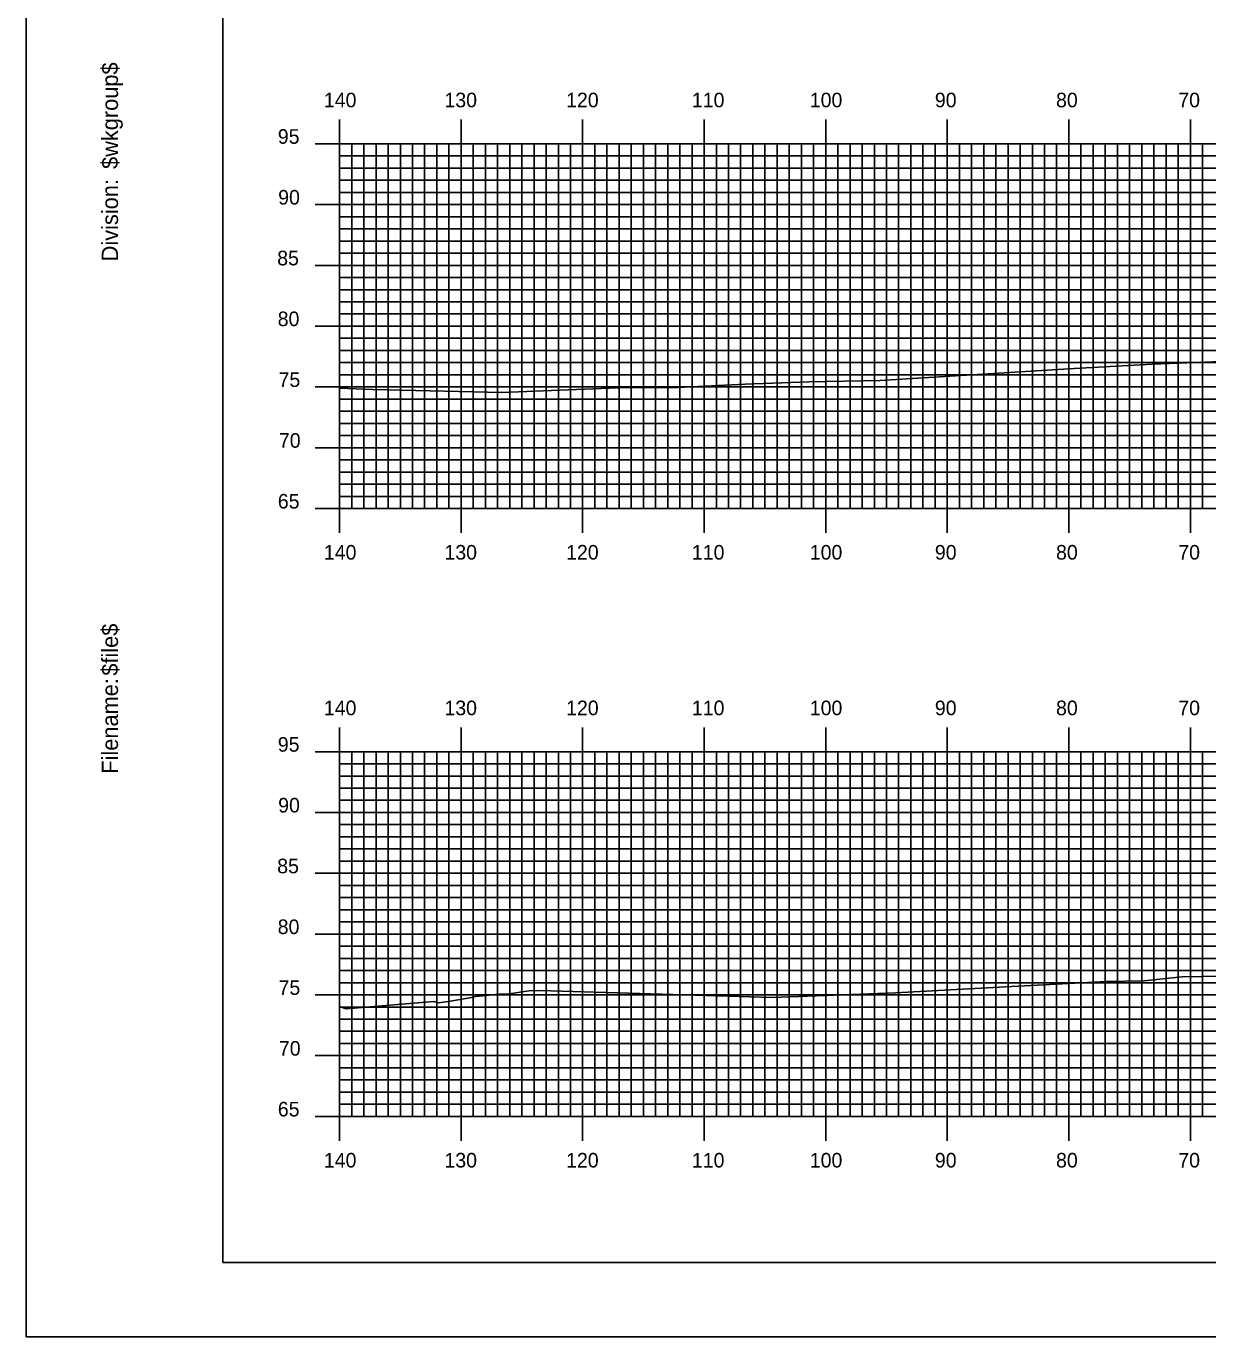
# Model space of a CAD drawing. Extents: x 1777138 to 1777481, y 442591 to 442811.
# Drawn here: x 1777138 to 1777235.2, y 442590.5 to 442698.3 of the extents above; entities that cross this region are included whole.
import ezdxf

# ---------------------------------------------------------------- set-up
doc = ezdxf.new("R2010")
doc.units = 0
for name, color, linetype in [('BORDER', 7, 'Continuous'), ('H_V ANNOTATION', 7, 'Continuous'), ('MAJOR', 7, 'Continuous'), ('MINOR', 7, 'Continuous'), ('PLOT BOUNDARY', 7, 'Continuous'), ('S_Roadway_Centerline', 7, 'Continuous')]:
    doc.layers.add(name, color=color, linetype=linetype)

msp = doc.modelspace()

# ---------------------------------------------------------------- linework, layer by layer
at = {"layer": 'BORDER'}
msp.add_lwpolyline([(1777154.16, 442596.67), (1777474.16, 442596.67), (1777474.16, 442806.67), (1777154.16, 442806.67)], close=True, dxfattribs=at)
at = {"layer": 'MAJOR'}
for p, q in [((1777163.76, 442690.67), (1777163.76, 442688.67)), ((1777173.76, 442690.67), (1777173.76, 442688.67)), ((1777183.76, 442690.67), (1777183.76, 442688.67)), ((1777193.76, 442690.67), (1777193.76, 442688.67)), ((1777203.76, 442690.67), (1777203.76, 442688.67)), ((1777213.76, 442690.67), (1777213.76, 442688.67)), ((1777223.76, 442690.67), (1777223.76, 442688.67)), ((1777233.76, 442690.67), (1777233.76, 442688.67)), ((1777161.76, 442688.67), (1777163.76, 442688.67)), ((1777163.76, 442688.67), (1777443.76, 442688.67)), ((1777163.76, 442658.67), (1777163.76, 442688.67)), ((1777163.76, 442658.67), (1777163.76, 442688.67)), ((1777163.76, 442688.67), (1777443.76, 442688.67)), ((1777173.76, 442658.67), (1777173.76, 442688.67)), ((1777183.76, 442658.67), (1777183.76, 442688.67)), ((1777193.76, 442658.67), (1777193.76, 442688.67)), ((1777203.76, 442658.67), (1777203.76, 442688.67)), ((1777213.76, 442658.67), (1777213.76, 442688.67)), ((1777223.76, 442658.67), (1777223.76, 442688.67)), ((1777233.76, 442658.67), (1777233.76, 442688.67)), ((1777161.76, 442683.67), (1777163.76, 442683.67)), ((1777163.76, 442683.67), (1777443.76, 442683.67)), ((1777161.76, 442678.67), (1777163.76, 442678.67)), ((1777163.76, 442678.67), (1777443.76, 442678.67)), ((1777161.76, 442673.67), (1777163.76, 442673.67)), ((1777163.76, 442673.67), (1777443.76, 442673.67)), ((1777161.76, 442668.67), (1777163.76, 442668.67)), ((1777163.76, 442668.67), (1777443.76, 442668.67)), ((1777161.76, 442663.67), (1777163.76, 442663.67)), ((1777163.76, 442663.67), (1777443.76, 442663.67)), ((1777161.76, 442658.67), (1777163.76, 442658.67)), ((1777163.76, 442658.67), (1777443.76, 442658.67)), ((1777163.76, 442658.67), (1777443.76, 442658.67)), ((1777163.76, 442656.66), (1777163.76, 442658.67)), ((1777173.76, 442656.66), (1777173.76, 442658.67)), ((1777183.76, 442656.66), (1777183.76, 442658.67)), ((1777193.76, 442656.66), (1777193.76, 442658.67)), ((1777203.76, 442656.66), (1777203.76, 442658.67)), ((1777213.76, 442656.66), (1777213.76, 442658.67)), ((1777223.76, 442656.66), (1777223.76, 442658.67)), ((1777233.76, 442656.66), (1777233.76, 442658.67)), ((1777163.76, 442640.67), (1777163.76, 442638.67)), ((1777173.76, 442640.67), (1777173.76, 442638.67)), ((1777183.76, 442640.67), (1777183.76, 442638.67)), ((1777193.76, 442640.67), (1777193.76, 442638.67)), ((1777203.76, 442640.67), (1777203.76, 442638.67)), ((1777213.76, 442640.67), (1777213.76, 442638.67)), ((1777223.76, 442640.67), (1777223.76, 442638.67)), ((1777233.76, 442640.67), (1777233.76, 442638.67)), ((1777161.76, 442638.67), (1777163.76, 442638.67)), ((1777163.76, 442638.67), (1777443.76, 442638.67)), ((1777163.76, 442608.67), (1777163.76, 442638.67)), ((1777163.76, 442608.67), (1777163.76, 442638.67)), ((1777163.76, 442638.67), (1777443.76, 442638.67)), ((1777173.76, 442608.67), (1777173.76, 442638.67)), ((1777183.76, 442608.67), (1777183.76, 442638.67)), ((1777193.76, 442608.67), (1777193.76, 442638.67)), ((1777203.76, 442608.67), (1777203.76, 442638.67)), ((1777213.76, 442608.67), (1777213.76, 442638.67)), ((1777223.76, 442608.67), (1777223.76, 442638.67)), ((1777233.76, 442608.67), (1777233.76, 442638.67)), ((1777161.76, 442633.67), (1777163.76, 442633.67)), ((1777163.76, 442633.67), (1777443.76, 442633.67)), ((1777161.76, 442628.67), (1777163.76, 442628.67)), ((1777163.76, 442628.67), (1777443.76, 442628.67)), ((1777161.76, 442623.67), (1777163.76, 442623.67)), ((1777163.76, 442623.67), (1777443.76, 442623.67)), ((1777161.76, 442618.67), (1777163.76, 442618.67)), ((1777163.76, 442618.67), (1777443.76, 442618.67)), ((1777161.76, 442613.67), (1777163.76, 442613.67)), ((1777163.76, 442613.67), (1777443.76, 442613.67)), ((1777161.76, 442608.67), (1777163.76, 442608.67)), ((1777163.76, 442608.67), (1777443.76, 442608.67)), ((1777163.76, 442608.67), (1777443.76, 442608.67)), ((1777163.76, 442606.66), (1777163.76, 442608.67)), ((1777173.76, 442606.66), (1777173.76, 442608.67)), ((1777183.76, 442606.66), (1777183.76, 442608.67)), ((1777193.76, 442606.66), (1777193.76, 442608.67)), ((1777203.76, 442606.66), (1777203.76, 442608.67)), ((1777213.76, 442606.66), (1777213.76, 442608.67)), ((1777223.76, 442606.66), (1777223.76, 442608.67)), ((1777233.76, 442606.66), (1777233.76, 442608.67))]:
    msp.add_line(p, q, dxfattribs=at)
at = {"layer": 'MINOR'}
for p, q in [((1777164.76, 442658.67), (1777164.76, 442688.67)), ((1777165.76, 442658.67), (1777165.76, 442688.67)), ((1777166.76, 442658.67), (1777166.76, 442688.67)), ((1777167.76, 442658.67), (1777167.76, 442688.67)), ((1777168.76, 442658.67), (1777168.76, 442688.67)), ((1777169.76, 442658.67), (1777169.76, 442688.67)), ((1777170.76, 442658.67), (1777170.76, 442688.67)), ((1777171.76, 442658.67), (1777171.76, 442688.67)), ((1777172.76, 442658.67), (1777172.76, 442688.67)), ((1777174.76, 442658.67), (1777174.76, 442688.67)), ((1777175.76, 442658.67), (1777175.76, 442688.67)), ((1777176.76, 442658.67), (1777176.76, 442688.67)), ((1777177.76, 442658.67), (1777177.76, 442688.67)), ((1777178.76, 442658.67), (1777178.76, 442688.67)), ((1777179.76, 442658.67), (1777179.76, 442688.67)), ((1777180.76, 442658.67), (1777180.76, 442688.67)), ((1777181.76, 442658.67), (1777181.76, 442688.67)), ((1777182.76, 442658.67), (1777182.76, 442688.67)), ((1777184.76, 442658.67), (1777184.76, 442688.67)), ((1777185.76, 442658.67), (1777185.76, 442688.67)), ((1777186.76, 442658.67), (1777186.76, 442688.67)), ((1777187.76, 442658.67), (1777187.76, 442688.67)), ((1777188.76, 442658.67), (1777188.76, 442688.67)), ((1777189.76, 442658.67), (1777189.76, 442688.67)), ((1777190.76, 442658.67), (1777190.76, 442688.67)), ((1777191.76, 442658.67), (1777191.76, 442688.67)), ((1777192.76, 442658.67), (1777192.76, 442688.67)), ((1777194.76, 442658.67), (1777194.76, 442688.67)), ((1777195.76, 442658.67), (1777195.76, 442688.67)), ((1777196.76, 442658.67), (1777196.76, 442688.67)), ((1777197.76, 442658.67), (1777197.76, 442688.67)), ((1777198.76, 442658.67), (1777198.76, 442688.67)), ((1777199.76, 442658.67), (1777199.76, 442688.67)), ((1777200.76, 442658.67), (1777200.76, 442688.67)), ((1777201.76, 442658.67), (1777201.76, 442688.67)), ((1777202.76, 442658.67), (1777202.76, 442688.67)), ((1777204.76, 442658.67), (1777204.76, 442688.67)), ((1777205.76, 442658.67), (1777205.76, 442688.67)), ((1777206.76, 442658.67), (1777206.76, 442688.67)), ((1777207.76, 442658.67), (1777207.76, 442688.67)), ((1777208.76, 442658.67), (1777208.76, 442688.67)), ((1777209.76, 442658.67), (1777209.76, 442688.67)), ((1777210.76, 442658.67), (1777210.76, 442688.67)), ((1777211.76, 442658.67), (1777211.76, 442688.67)), ((1777212.76, 442658.67), (1777212.76, 442688.67)), ((1777214.76, 442658.67), (1777214.76, 442688.67)), ((1777215.76, 442658.67), (1777215.76, 442688.67)), ((1777216.76, 442658.67), (1777216.76, 442688.67)), ((1777217.76, 442658.67), (1777217.76, 442688.67)), ((1777218.76, 442658.67), (1777218.76, 442688.67)), ((1777219.76, 442658.67), (1777219.76, 442688.67)), ((1777220.76, 442658.67), (1777220.76, 442688.67)), ((1777221.76, 442658.67), (1777221.76, 442688.67)), ((1777222.76, 442658.67), (1777222.76, 442688.67)), ((1777224.76, 442658.67), (1777224.76, 442688.67)), ((1777225.76, 442658.67), (1777225.76, 442688.67)), ((1777226.76, 442658.67), (1777226.76, 442688.67)), ((1777227.76, 442658.67), (1777227.76, 442688.67)), ((1777228.76, 442658.67), (1777228.76, 442688.67)), ((1777229.76, 442658.67), (1777229.76, 442688.67)), ((1777230.76, 442658.67), (1777230.76, 442688.67)), ((1777231.76, 442658.67), (1777231.76, 442688.67)), ((1777232.76, 442658.67), (1777232.76, 442688.67)), ((1777234.76, 442658.67), (1777234.76, 442688.67)), ((1777163.76, 442687.67), (1777443.76, 442687.67)), ((1777163.76, 442687.67), (1777165.77, 442687.67)), ((1777163.76, 442686.67), (1777443.76, 442686.67)), ((1777163.76, 442686.67), (1777165.77, 442686.67)), ((1777163.76, 442685.67), (1777443.76, 442685.67)), ((1777163.76, 442685.67), (1777165.77, 442685.67)), ((1777163.76, 442684.67), (1777443.76, 442684.67)), ((1777163.76, 442684.67), (1777165.77, 442684.67)), ((1777163.76, 442682.67), (1777443.76, 442682.67)), ((1777163.76, 442682.67), (1777165.77, 442682.67)), ((1777163.76, 442681.67), (1777443.76, 442681.67)), ((1777163.76, 442681.67), (1777165.77, 442681.67)), ((1777163.76, 442680.67), (1777443.76, 442680.67)), ((1777163.76, 442680.67), (1777165.77, 442680.67)), ((1777163.76, 442679.67), (1777443.76, 442679.67)), ((1777163.76, 442679.67), (1777165.77, 442679.67)), ((1777163.76, 442677.67), (1777443.76, 442677.67)), ((1777163.76, 442677.67), (1777165.77, 442677.67)), ((1777163.76, 442676.67), (1777443.76, 442676.67)), ((1777163.76, 442676.67), (1777165.77, 442676.67)), ((1777163.76, 442675.67), (1777443.76, 442675.67)), ((1777163.76, 442675.67), (1777165.77, 442675.67)), ((1777163.76, 442674.67), (1777443.76, 442674.67)), ((1777163.76, 442674.67), (1777165.77, 442674.67)), ((1777163.76, 442672.67), (1777443.76, 442672.67)), ((1777163.76, 442672.67), (1777165.77, 442672.67)), ((1777163.76, 442671.67), (1777443.76, 442671.67)), ((1777163.76, 442671.67), (1777165.77, 442671.67)), ((1777163.76, 442670.67), (1777443.76, 442670.67)), ((1777163.76, 442670.67), (1777165.77, 442670.67)), ((1777163.76, 442669.67), (1777443.76, 442669.67)), ((1777163.76, 442669.67), (1777165.77, 442669.67)), ((1777163.76, 442667.67), (1777443.76, 442667.67)), ((1777163.76, 442667.67), (1777165.77, 442667.67)), ((1777163.76, 442666.67), (1777443.76, 442666.67)), ((1777163.76, 442666.67), (1777165.77, 442666.67)), ((1777163.76, 442665.67), (1777443.76, 442665.67)), ((1777163.76, 442665.67), (1777165.77, 442665.67)), ((1777163.76, 442664.67), (1777443.76, 442664.67)), ((1777163.76, 442664.67), (1777165.77, 442664.67)), ((1777163.76, 442662.67), (1777443.76, 442662.67)), ((1777163.76, 442662.67), (1777165.77, 442662.67)), ((1777163.76, 442661.67), (1777443.76, 442661.67)), ((1777163.76, 442661.67), (1777165.77, 442661.67)), ((1777163.76, 442660.67), (1777443.76, 442660.67)), ((1777163.76, 442660.67), (1777165.77, 442660.67)), ((1777163.76, 442659.67), (1777443.76, 442659.67)), ((1777163.76, 442659.67), (1777165.77, 442659.67)), ((1777164.76, 442608.67), (1777164.76, 442638.67)), ((1777165.76, 442608.67), (1777165.76, 442638.67)), ((1777166.76, 442608.67), (1777166.76, 442638.67)), ((1777167.76, 442608.67), (1777167.76, 442638.67)), ((1777168.76, 442608.67), (1777168.76, 442638.67)), ((1777169.76, 442608.67), (1777169.76, 442638.67)), ((1777170.76, 442608.67), (1777170.76, 442638.67)), ((1777171.76, 442608.67), (1777171.76, 442638.67)), ((1777172.76, 442608.67), (1777172.76, 442638.67)), ((1777174.76, 442608.67), (1777174.76, 442638.67)), ((1777175.76, 442608.67), (1777175.76, 442638.67)), ((1777176.76, 442608.67), (1777176.76, 442638.67)), ((1777177.76, 442608.67), (1777177.76, 442638.67)), ((1777178.76, 442608.67), (1777178.76, 442638.67)), ((1777179.76, 442608.67), (1777179.76, 442638.67)), ((1777180.76, 442608.67), (1777180.76, 442638.67)), ((1777181.76, 442608.67), (1777181.76, 442638.67)), ((1777182.76, 442608.67), (1777182.76, 442638.67)), ((1777184.76, 442608.67), (1777184.76, 442638.67)), ((1777185.76, 442608.67), (1777185.76, 442638.67)), ((1777186.76, 442608.67), (1777186.76, 442638.67)), ((1777187.76, 442608.67), (1777187.76, 442638.67)), ((1777188.76, 442608.67), (1777188.76, 442638.67)), ((1777189.76, 442608.67), (1777189.76, 442638.67)), ((1777190.76, 442608.67), (1777190.76, 442638.67)), ((1777191.76, 442608.67), (1777191.76, 442638.67)), ((1777192.76, 442608.67), (1777192.76, 442638.67)), ((1777194.76, 442608.67), (1777194.76, 442638.67)), ((1777195.76, 442608.67), (1777195.76, 442638.67)), ((1777196.76, 442608.67), (1777196.76, 442638.67)), ((1777197.76, 442608.67), (1777197.76, 442638.67)), ((1777198.76, 442608.67), (1777198.76, 442638.67)), ((1777199.76, 442608.67), (1777199.76, 442638.67)), ((1777200.76, 442608.67), (1777200.76, 442638.67)), ((1777201.76, 442608.67), (1777201.76, 442638.67)), ((1777202.76, 442608.67), (1777202.76, 442638.67)), ((1777204.76, 442608.67), (1777204.76, 442638.67)), ((1777205.76, 442608.67), (1777205.76, 442638.67)), ((1777206.76, 442608.67), (1777206.76, 442638.67)), ((1777207.76, 442608.67), (1777207.76, 442638.67)), ((1777208.76, 442608.67), (1777208.76, 442638.67)), ((1777209.76, 442608.67), (1777209.76, 442638.67)), ((1777210.76, 442608.67), (1777210.76, 442638.67)), ((1777211.76, 442608.67), (1777211.76, 442638.67)), ((1777212.76, 442608.67), (1777212.76, 442638.67)), ((1777214.76, 442608.67), (1777214.76, 442638.67)), ((1777215.76, 442608.67), (1777215.76, 442638.67)), ((1777216.76, 442608.67), (1777216.76, 442638.67)), ((1777217.76, 442608.67), (1777217.76, 442638.67)), ((1777218.76, 442608.67), (1777218.76, 442638.67)), ((1777219.76, 442608.67), (1777219.76, 442638.67)), ((1777220.76, 442608.67), (1777220.76, 442638.67)), ((1777221.76, 442608.67), (1777221.76, 442638.67)), ((1777222.76, 442608.67), (1777222.76, 442638.67)), ((1777224.76, 442608.67), (1777224.76, 442638.67)), ((1777225.76, 442608.67), (1777225.76, 442638.67)), ((1777226.76, 442608.67), (1777226.76, 442638.67)), ((1777227.76, 442608.67), (1777227.76, 442638.67)), ((1777228.76, 442608.67), (1777228.76, 442638.67)), ((1777229.76, 442608.67), (1777229.76, 442638.67)), ((1777230.76, 442608.67), (1777230.76, 442638.67)), ((1777231.76, 442608.67), (1777231.76, 442638.67)), ((1777232.76, 442608.67), (1777232.76, 442638.67)), ((1777234.76, 442608.67), (1777234.76, 442638.67)), ((1777163.76, 442637.67), (1777443.76, 442637.67)), ((1777163.76, 442637.67), (1777165.77, 442637.67)), ((1777163.76, 442636.67), (1777443.76, 442636.67)), ((1777163.76, 442636.67), (1777165.77, 442636.67)), ((1777163.76, 442635.67), (1777443.76, 442635.67)), ((1777163.76, 442635.67), (1777165.77, 442635.67)), ((1777163.76, 442634.67), (1777443.76, 442634.67)), ((1777163.76, 442634.67), (1777165.77, 442634.67)), ((1777163.76, 442632.67), (1777443.76, 442632.67)), ((1777163.76, 442632.67), (1777165.77, 442632.67)), ((1777163.76, 442631.67), (1777443.76, 442631.67)), ((1777163.76, 442631.67), (1777165.77, 442631.67)), ((1777163.76, 442630.67), (1777443.76, 442630.67)), ((1777163.76, 442630.67), (1777165.77, 442630.67)), ((1777163.76, 442629.67), (1777443.76, 442629.67)), ((1777163.76, 442629.67), (1777165.77, 442629.67)), ((1777163.76, 442627.67), (1777443.76, 442627.67)), ((1777163.76, 442627.67), (1777165.77, 442627.67)), ((1777163.76, 442626.67), (1777443.76, 442626.67)), ((1777163.76, 442626.67), (1777165.77, 442626.67)), ((1777163.76, 442625.67), (1777443.76, 442625.67)), ((1777163.76, 442625.67), (1777165.77, 442625.67)), ((1777163.76, 442624.67), (1777443.76, 442624.67)), ((1777163.76, 442624.67), (1777165.77, 442624.67)), ((1777163.76, 442622.67), (1777443.76, 442622.67)), ((1777163.76, 442622.67), (1777165.77, 442622.67)), ((1777163.76, 442621.67), (1777443.76, 442621.67)), ((1777163.76, 442621.67), (1777165.77, 442621.67)), ((1777163.76, 442620.67), (1777443.76, 442620.67)), ((1777163.76, 442620.67), (1777165.77, 442620.67)), ((1777163.76, 442619.67), (1777443.76, 442619.67)), ((1777163.76, 442619.67), (1777165.77, 442619.67)), ((1777163.76, 442617.67), (1777443.76, 442617.67)), ((1777163.76, 442617.67), (1777165.77, 442617.67)), ((1777163.76, 442616.67), (1777443.76, 442616.67)), ((1777163.76, 442616.67), (1777165.77, 442616.67)), ((1777163.76, 442615.67), (1777443.76, 442615.67)), ((1777163.76, 442615.67), (1777165.77, 442615.67)), ((1777163.76, 442614.67), (1777443.76, 442614.67)), ((1777163.76, 442614.67), (1777165.77, 442614.67)), ((1777163.76, 442612.67), (1777443.76, 442612.67)), ((1777163.76, 442612.67), (1777165.77, 442612.67)), ((1777163.76, 442611.67), (1777443.76, 442611.67)), ((1777163.76, 442611.67), (1777165.77, 442611.67)), ((1777163.76, 442610.67), (1777443.76, 442610.67)), ((1777163.76, 442610.67), (1777165.77, 442610.67)), ((1777163.76, 442609.67), (1777443.76, 442609.67)), ((1777163.76, 442609.67), (1777165.77, 442609.67))]:
    msp.add_line(p, q, dxfattribs=at)
at = {"layer": 'PLOT BOUNDARY'}
msp.add_lwpolyline([(1777137.98, 442590.55), (1777477.98, 442590.55), (1777477.98, 442810.55), (1777137.98, 442810.55)], close=True, dxfattribs=at)
at = {"layer": 'S_Roadway_Centerline'}
for points in [[(1777163.76, 442668.56), (1777166.51, 442668.46), (1777177.12, 442668.2), (1777186.65, 442668.61), (1777191.6, 442668.63), (1777197.13, 442668.89), (1777202.41, 442669.09), (1777208.25, 442669.2), (1777224.2, 442670.18), (1777230.62, 442670.54), (1777238.5, 442670.85)], [(1777163.76, 442617.72), (1777164.3, 442617.52), (1777171.52, 442618.11), (1777171.9, 442618.02), (1777172.72, 442618.11), (1777174.78, 442618.49), (1777174.81, 442618.51), (1777174.96, 442618.53), (1777176.9, 442618.72), (1777177.54, 442618.74), (1777179.32, 442619.01), (1777180.23, 442619.02), (1777199.39, 442618.46), (1777209.49, 442618.85), (1777218.56, 442619.32), (1777226.86, 442619.76), (1777229.95, 442619.82), (1777233.07, 442620.16), (1777249.83, 442620.42)]]:
    msp.add_lwpolyline(points, dxfattribs=at)

# ---------------------------------------------------------------- texts
at = {"layer": 'BORDER'}
for s, p in [('$wkgroup$', (1777145.53, 442686.6)), ('Division:', (1777145.53, 442679)), ('$file$', (1777145.53, 442644.92)), ('Filename:', (1777145.53, 442636.86))]:
    msp.add_text(s, height=1.339, rotation=90, dxfattribs=at).set_placement(p)
at = {"layer": 'H_V ANNOTATION'}
for s, p in [('140', (1777162.47, 442691.67)), ('130', (1777172.39, 442691.67)), ('120', (1777182.4, 442691.67)), ('110', (1777192.75, 442691.67)), ('100', (1777202.45, 442691.67)), ('90', (1777212.74, 442691.67)), ('80', (1777222.71, 442691.67)), ('70', (1777232.77, 442691.67)), ('95', (1777158.68, 442688.67)), ('90', (1777158.71, 442683.67)), ('85', (1777158.63, 442678.67)), ('80', (1777158.67, 442673.67)), ('75', (1777158.74, 442668.67)), ('70', (1777158.77, 442663.67)), ('65', (1777158.68, 442658.67)), ('140', (1777162.47, 442654.47)), ('130', (1777172.39, 442654.47)), ('120', (1777182.4, 442654.47)), ('110', (1777192.75, 442654.47)), ('100', (1777202.45, 442654.47)), ('90', (1777212.74, 442654.47)), ('80', (1777222.71, 442654.47)), ('70', (1777232.77, 442654.47)), ('140', (1777162.47, 442641.67)), ('130', (1777172.39, 442641.67)), ('120', (1777182.4, 442641.67)), ('110', (1777192.75, 442641.67)), ('100', (1777202.45, 442641.67)), ('90', (1777212.74, 442641.67)), ('80', (1777222.71, 442641.67)), ('70', (1777232.77, 442641.67)), ('95', (1777158.68, 442638.67)), ('90', (1777158.71, 442633.67)), ('85', (1777158.63, 442628.67)), ('80', (1777158.67, 442623.67)), ('75', (1777158.74, 442618.67)), ('70', (1777158.77, 442613.67)), ('65', (1777158.68, 442608.67)), ('140', (1777162.47, 442604.47)), ('130', (1777172.39, 442604.47)), ('120', (1777182.4, 442604.47)), ('110', (1777192.75, 442604.47)), ('100', (1777202.45, 442604.47)), ('90', (1777212.74, 442604.47)), ('80', (1777222.71, 442604.47)), ('70', (1777232.77, 442604.47))]:
    msp.add_text(s, height=1.2, dxfattribs=at).set_placement(p)
at = {"layer": 'MAJOR'}
for p in [(1777163.75, 442658.67), (1777163.75, 442608.67)]:
    msp.add_text('-', height=0.012, dxfattribs=at).set_placement(p)

doc.saveas('drawing.dxf')
